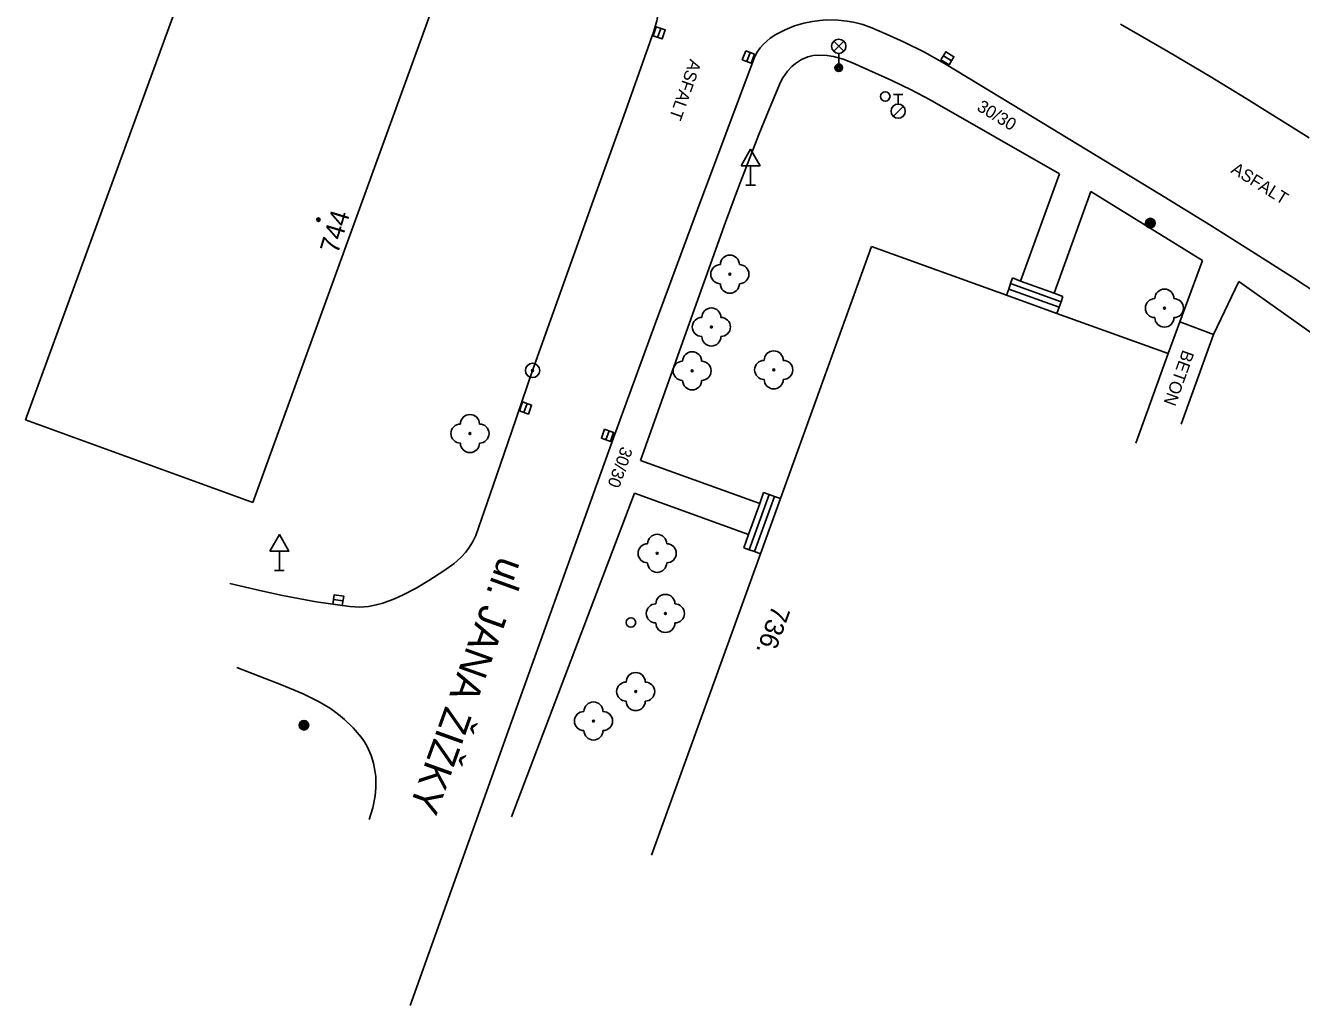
# Model space of a CAD drawing. Extents: x -538441 to -536770, y -1181008 to -1179809.
# Drawn here: x -538298 to -538231.1, y -1181006.5 to -1180955.1 of the extents above; entities that cross this region are included whole.
import ezdxf

# ---------------------------------------------------------------- set-up
doc = ezdxf.new("R2010")
doc.units = 0
for name, color, linetype in [('Vrstva 10', 7, 'Continuous'), ('Vrstva 11', 7, 'Continuous'), ('Vrstva 21', 7, 'Continuous'), ('Vrstva 22', 7, 'Continuous'), ('Vrstva 25', 7, 'Continuous'), ('Vrstva 27', 7, 'Continuous'), ('Vrstva 28', 7, 'Continuous'), ('Vrstva 33', 7, 'Continuous'), ('Vrstva 34', 7, 'Continuous'), ('Vrstva 39', 7, 'Continuous'), ('Vrstva 40', 7, 'Continuous'), ('Vrstva 47', 7, 'Continuous'), ('Vrstva 49', 7, 'Continuous'), ('Vrstva 5', 7, 'Continuous')]:
    doc.layers.add(name, color=color, linetype=linetype)

msp = doc.modelspace()

# ---------------------------------------------------------------- linework, layer by layer
at = {"layer": 'Vrstva 10'}
for p, q in [((-538249.82, -1180957.11), (-538245.698, -1180959.61)), ((-538245.698, -1180959.61), (-538238.525, -1180963.966)), ((-538271.43, -1180973.21), (-538268.247, -1180964.31)), ((-538264.992, -1180970.756), (-538262.77, -1180964.77)), ((-538267.19, -1180976.75), (-538264.992, -1180970.756)), ((-538272.526, -1180991.633), (-538267.19, -1180976.75)), ((-538277.85, -1181006.52), (-538272.526, -1180991.633))]:
    msp.add_line(p, q, dxfattribs=at)
for points in [[(-538265.07, -1180955.41), (-538264.914, -1180954.878), (-538264.822, -1180954.4), (-538264.774, -1180953.974), (-538264.758, -1180953.597), (-538264.786, -1180952.934), (-538264.853, -1180952.437), (-538264.93, -1180952.066), (-538265.086, -1180951.517), (-538265.29, -1180950.98), (-538265.495, -1180950.544), (-538265.697, -1180950.176), (-538265.892, -1180949.867), (-538266.272, -1180949.362), (-538266.592, -1180949.02)], [(-538258.96, -1180955.788), (-538258.661, -1180955.591), (-538258.182, -1180955.34), (-538257.69, -1180955.14), (-538257.195, -1180954.99), (-538256.75, -1180954.897), (-538256.355, -1180954.846), (-538256.006, -1180954.824), (-538255.394, -1180954.835), (-538254.94, -1180954.884), (-538254.604, -1180954.944), (-538254.112, -1180955.07), (-538253.64, -1180955.24), (-538252.665, -1180955.655), (-538251.94, -1180955.984), (-538250.867, -1180956.517), (-538249.82, -1180957.11)], [(-538240.601, -1180955.041), (-538238.083, -1180956.494), (-538235.895, -1180957.79), (-538233.994, -1180958.944)], [(-538268.247, -1180964.31), (-538266.647, -1180959.862), (-538265.07, -1180955.41)], [(-538262.77, -1180964.77), (-538261.3, -1180960.798), (-538259.81, -1180956.83), (-538259.662, -1180956.527), (-538259.492, -1180956.285), (-538259.316, -1180956.091), (-538258.96, -1180955.788)], [(-538233.994, -1180958.944), (-538230.696, -1180961.013)], [(-538238.525, -1180963.966), (-538235.857, -1180965.613), (-538233.535, -1180967.069), (-538231.514, -1180968.357)], [(-538231.514, -1180968.357), (-538228.007, -1180970.652), (-538225.404, -1180972.415), (-538223.468, -1180973.766)], [(-538274.41, -1180981.86), (-538273.645, -1180979.699), (-538272.541, -1180976.452), (-538271.43, -1180973.21)], [(-538282.778, -1180985.34), (-538281.01, -1180985.6), (-538280.483, -1180985.626), (-538280.024, -1180985.588), (-538279.624, -1180985.511), (-538279.276, -1180985.416), (-538278.668, -1180985.191), (-538278.215, -1180984.983), (-538277.536, -1180984.622), (-538276.86, -1180984.22), (-538276.084, -1180983.726), (-538275.548, -1180983.334), (-538275.187, -1180983.016), (-538274.945, -1180982.76), (-538274.783, -1180982.554), (-538274.573, -1180982.223), (-538274.41, -1180981.86)], [(-538287.312, -1180984.389), (-538285.734, -1180984.76), (-538284.551, -1180985.012), (-538282.778, -1180985.34)], [(-538286.934, -1180988.786), (-538284.6, -1180989.7), (-538283.45, -1180990.175), (-538282.624, -1180990.585), (-538282.03, -1180990.945), (-538281.602, -1180991.255), (-538281.291, -1180991.513), (-538280.844, -1180991.949), (-538280.42, -1180992.45), (-538280.245, -1180992.698), (-538280.103, -1180992.938), (-538279.893, -1180993.401), (-538279.765, -1180993.818), (-538279.692, -1180994.189), (-538279.656, -1180994.517)], [(-538279.656, -1180994.517), (-538279.65, -1180995.092), (-538279.69, -1180995.521), (-538279.809, -1180996.153), (-538279.99, -1180996.76)]]:
    msp.add_lwpolyline(points, dxfattribs=at)
at = {"layer": 'Vrstva 11'}
for p, q in [((-538245.834, -1180968.526), (-538243.8, -1180962.9)), ((-538244.077, -1180969.161), (-538242.15, -1180963.83)), ((-538242.15, -1180963.83), (-538236.29, -1180967.44)), ((-538263.54, -1180971.685), (-538261.31, -1180965.44)), ((-538235.71, -1180971.32), (-538234.39, -1180968.55)), ((-538234.39, -1180968.55), (-538226.57, -1180974.105)), ((-538246.458, -1180968.938), (-538243.813, -1180969.894)), ((-538246.356, -1180968.656), (-538243.711, -1180969.612)), ((-538237.485, -1180970.662), (-538235.71, -1180971.32)), ((-538265.77, -1180977.93), (-538263.54, -1180971.685)), ((-538237.407, -1180976.023), (-538235.71, -1180971.32)), ((-538259.512, -1180980.191), (-538265.77, -1180977.93)), ((-538272.54, -1180996.63), (-538266.09, -1180979.65)), ((-538260.099, -1180981.815), (-538266.09, -1180979.65)), ((-538259.02, -1180979.713), (-538260.067, -1180982.611)), ((-538258.738, -1180979.815), (-538259.785, -1180982.713))]:
    msp.add_line(p, q, dxfattribs=at)
for points in [[(-538261.31, -1180965.44), (-538260.634, -1180963.589), (-538259.568, -1180960.835), (-538259.005, -1180959.462), (-538258.42, -1180958.09), (-538258.308, -1180957.868), (-538258.055, -1180957.505), (-538257.824, -1180957.263), (-538257.633, -1180957.102), (-538257.322, -1180956.902), (-538256.99, -1180956.76)], [(-538256.99, -1180956.76), (-538256.706, -1180956.691), (-538256.45, -1180956.664), (-538255.991, -1180956.683), (-538255.645, -1180956.742), (-538255.134, -1180956.888), (-538254.65, -1180957.08), (-538252.59, -1180958), (-538251.573, -1180958.488), (-538250.58, -1180959.02)], [(-538250.58, -1180959.02), (-538247.19, -1180960.96), (-538243.8, -1180962.9)], [(-538236.29, -1180967.44), (-538237.485, -1180970.662), (-538238.1, -1180972.32)], [(-538246.576, -1180969.262), (-538246.458, -1180968.938), (-538246.356, -1180968.656), (-538246.25, -1180968.36)], [(-538246.25, -1180968.36), (-538245.834, -1180968.526), (-538244.077, -1180969.161), (-538243.61, -1180969.33)], [(-538243.93, -1180970.217), (-538243.813, -1180969.894), (-538243.711, -1180969.612), (-538243.61, -1180969.33)], [(-538259.31, -1180979.61), (-538259.512, -1180980.191), (-538260.099, -1180981.815), (-538260.35, -1180982.51)], [(-538258.427, -1180979.929), (-538258.738, -1180979.815), (-538259.02, -1180979.713), (-538259.31, -1180979.61)], [(-538259.474, -1180982.827), (-538259.785, -1180982.713), (-538260.067, -1180982.611), (-538260.35, -1180982.51)]]:
    msp.add_lwpolyline(points, dxfattribs=at)
at = {"layer": 'Vrstva 21'}
for radius in [0.375, 0.05]:
    msp.add_circle((-538271.43, -1180973.21), radius, dxfattribs=at)
at = {"layer": 'Vrstva 22'}
for centre in [(-538261.08, -1180968.16), (-538238.29, -1180969.94), (-538262.05, -1180970.93), (-538263.06, -1180973.23), (-538258.78, -1180973.18), (-538274.71, -1180976.52), (-538264.892, -1180982.802), (-538264.463, -1180985.955), (-538266.02, -1180990.054), (-538268.234, -1180991.598)]:
    msp.add_circle(centre, 0.05, dxfattribs=at)
for centre, start, end in [((-538261.08, -1180967.66), 0, 180), ((-538261.58, -1180968.16), 90, 270), ((-538260.58, -1180968.16), 270, 90), ((-538261.08, -1180968.66), 180, 0), ((-538238.29, -1180969.44), 0, 180), ((-538238.79, -1180969.94), 90, 270), ((-538237.79, -1180969.94), 270, 90), ((-538262.55, -1180970.93), 90, 270), ((-538262.05, -1180970.43), 0, 180), ((-538261.55, -1180970.93), 270, 90), ((-538238.29, -1180970.44), 180, 0), ((-538262.05, -1180971.43), 180, 0), ((-538263.06, -1180972.73), 0, 180), ((-538258.78, -1180972.68), 0, 180), ((-538263.56, -1180973.23), 90, 270), ((-538262.56, -1180973.23), 270, 90), ((-538259.28, -1180973.18), 90, 270), ((-538258.28, -1180973.18), 270, 90), ((-538263.06, -1180973.73), 180, 0), ((-538258.78, -1180973.68), 180, 0), ((-538274.71, -1180976.02), 0, 180), ((-538275.21, -1180976.52), 90, 270), ((-538274.21, -1180976.52), 270, 90), ((-538274.71, -1180977.02), 180, 0), ((-538264.892, -1180982.302), 0, 180), ((-538265.392, -1180982.802), 90, 270), ((-538264.392, -1180982.802), 270, 90), ((-538264.892, -1180983.302), 180, 0), ((-538264.463, -1180985.455), 0, 180), ((-538264.963, -1180985.955), 90, 270), ((-538263.963, -1180985.955), 270, 90), ((-538264.463, -1180986.455), 180, 0), ((-538266.02, -1180989.554), 0, 180), ((-538266.52, -1180990.054), 90, 270), ((-538265.52, -1180990.054), 270, 90), ((-538268.234, -1180991.098), 0, 180), ((-538266.02, -1180990.554), 180, 0), ((-538268.734, -1180991.598), 90, 270), ((-538267.734, -1180991.598), 270, 90), ((-538268.234, -1180992.098), 180, 0)]:
    msp.add_arc(centre, 0.5, start, end, dxfattribs=at)
at = {"layer": 'Vrstva 25'}
for centre, radius in [((-538239.03, -1180965.48), 0.25), ((-538239.03, -1180965.48), 0.2), ((-538239.03, -1180965.48), 0.15), ((-538239.03, -1180965.48), 0.1), ((-538239.03, -1180965.48), 0.05), ((-538283.42, -1180991.82), 0.25), ((-538283.42, -1180991.82), 0.2), ((-538283.42, -1180991.82), 0.15), ((-538283.42, -1180991.82), 0.1), ((-538283.42, -1180991.82), 0.05)]:
    msp.add_circle(centre, radius, dxfattribs=at)
at = {"layer": 'Vrstva 27'}
for p, q in [((-538264.709, -1180955.27), (-538264.867, -1180955.744)), ((-538260.016, -1180956.535), (-538260.194, -1180957.003)), ((-538249.884, -1180956.709), (-538249.456, -1180956.967)), ((-538271.719, -1180974.942), (-538271.881, -1180975.416)), ((-538267.412, -1180976.383), (-538267.582, -1180976.853)), ((-538281.864, -1180985.222), (-538281.37, -1180985.294))]:
    msp.add_line(p, q, dxfattribs=at)
for points in [[(-538264.946, -1180955.191), (-538265.104, -1180955.665), (-538264.63, -1180955.823), (-538264.472, -1180955.349)], [(-538260.25, -1180956.447), (-538260.427, -1180956.914), (-538259.96, -1180957.091), (-538259.783, -1180956.624)], [(-538250.013, -1180956.922), (-538249.586, -1180957.181), (-538249.327, -1180956.754), (-538249.754, -1180956.495)], [(-538271.956, -1180974.862), (-538272.117, -1180975.335), (-538271.644, -1180975.496), (-538271.483, -1180975.023)], [(-538267.648, -1180976.298), (-538267.817, -1180976.769), (-538267.346, -1180976.938), (-538267.177, -1180976.467)], [(-538281.901, -1180985.469), (-538281.406, -1180985.542), (-538281.333, -1180985.047), (-538281.828, -1180984.974)]]:
    msp.add_lwpolyline(points, close=True, dxfattribs=at)
at = {"layer": 'Vrstva 28'}
for p, q in [((-538252.503, -1180958.733), (-538252.003, -1180958.733)), ((-538252.253, -1180959.233), (-538252.253, -1180958.733)), ((-538252.511, -1180959.88), (-538251.981, -1180959.35))]:
    msp.add_line(p, q, dxfattribs=at)
for centre, radius in [((-538252.931, -1180958.837), 0.25), ((-538252.253, -1180959.608), 0.375), ((-538266.27, -1180986.43), 0.25)]:
    msp.add_circle(centre, radius, dxfattribs=at)
at = {"layer": 'Vrstva 33'}
for p, q in [((-538255.635, -1180956.47), (-538255.105, -1180955.94)), ((-538255.635, -1180955.94), (-538255.105, -1180956.47)), ((-538255.37, -1180956.58), (-538255.37, -1180957.33))]:
    msp.add_line(p, q, dxfattribs=at)
for centre, radius in [((-538255.37, -1180956.205), 0.375), ((-538255.37, -1180957.33), 0.2), ((-538255.37, -1180957.33), 0.145), ((-538255.37, -1180957.33), 0.0876)]:
    msp.add_circle(centre, radius, dxfattribs=at)
at = {"layer": 'Vrstva 34'}
for p, q in [((-538259.994, -1180962.474), (-538259.994, -1180963.492)), ((-538260.244, -1180963.492), (-538259.744, -1180963.492)), ((-538284.707, -1180982.682), (-538284.707, -1180983.7)), ((-538284.957, -1180983.7), (-538284.457, -1180983.7))]:
    msp.add_line(p, q, dxfattribs=at)
for points in [[(-538260.494, -1180962.474), (-538259.494, -1180962.474), (-538259.994, -1180961.608)], [(-538285.207, -1180982.682), (-538284.207, -1180982.682), (-538284.707, -1180981.816)]]:
    msp.add_lwpolyline(points, close=True, dxfattribs=at)
at = {"layer": 'Vrstva 39'}
for radius in [0.09, 0.0398]:
    msp.add_circle((-538282.66, -1180965.3), radius, dxfattribs=at)
at = {"layer": 'Vrstva 5'}
for p, q in [((-538287.82, -1180947.88), (-538298.02, -1180975.8)), ((-538286.1, -1180980.13), (-538275.95, -1180952.16)), ((-538239.797, -1180977.023), (-538238.1, -1180972.32)), ((-538298.02, -1180975.8), (-538286.1, -1180980.13))]:
    msp.add_line(p, q, dxfattribs=at)
for points in [[(-538253.65, -1180966.71), (-538258.427, -1180979.929)], [(-538246.576, -1180969.262), (-538253.65, -1180966.71)], [(-538243.93, -1180970.217), (-538246.576, -1180969.262)], [(-538238.1, -1180972.32), (-538243.93, -1180970.217)], [(-538258.427, -1180979.929), (-538259.474, -1180982.827)], [(-538259.474, -1180982.827), (-538265.187, -1180998.636)]]:
    msp.add_lwpolyline(points, dxfattribs=at)

# ---------------------------------------------------------------- texts
at = {"layer": 'Vrstva 40'}
for s, rotation, p in [('ASFALT', 250.34763, (-538263.17, -1180956.841)), ('30/30', 328.82498, (-538248.171, -1180959.536)), ('ASFALT', 327.98196, (-538234.848, -1180962.804)), ('BETON', 250.15886, (-538237.325, -1180972.091)), ('30/30', 250.23769, (-538266.772, -1180977.161))]:
    msp.add_text(s, height=0.65, rotation=rotation, dxfattribs=at).set_placement(p)
at = {"layer": 'Vrstva 47'}
for s, rotation, p in [('744', 73.24387, (-538281.643, -1180967.133)), ('736.', 250.13187, (-538258.836, -1180985.474))]:
    msp.add_text(s, height=1, rotation=rotation, dxfattribs=at).set_placement(p)
at = {"layer": 'Vrstva 49'}
msp.add_text('ul. JANA ŽIŽKY', height=1.5, rotation=250.30139, dxfattribs=at).set_placement((-538273.172, -1180982.904))

doc.saveas('drawing.dxf')
